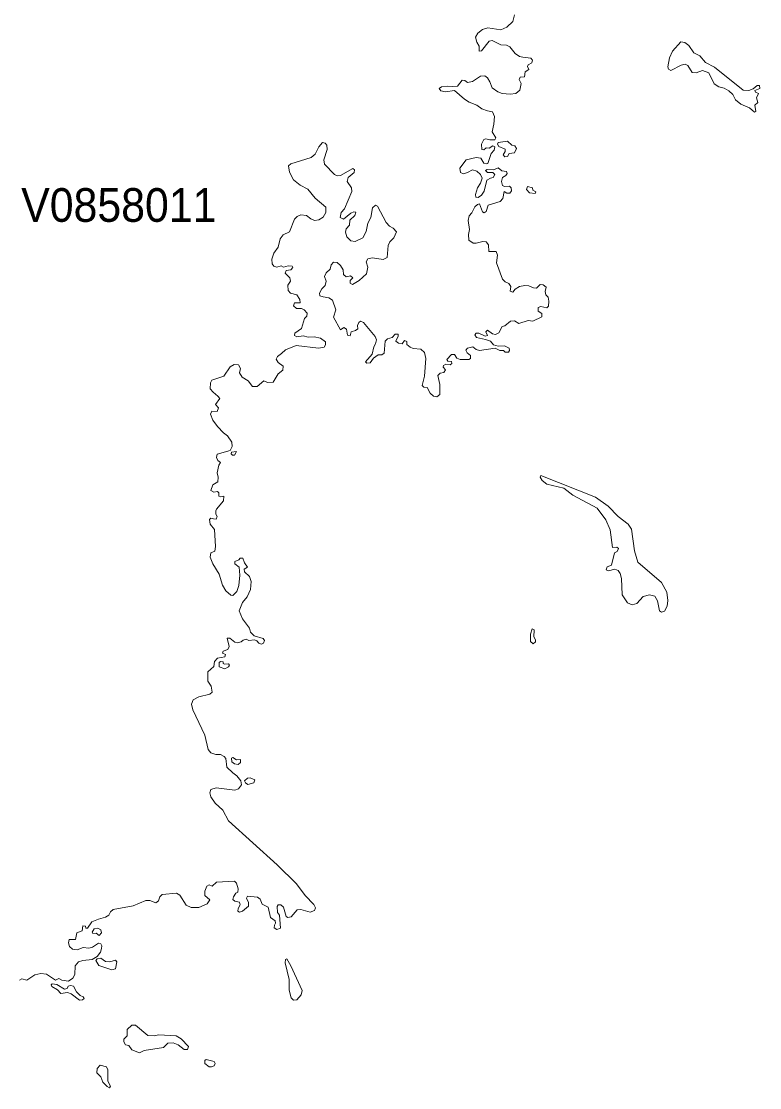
# Model space of a CAD drawing. Extents: x 369010 to 735936, y 6377141 to 6616555.
# Drawn here: x 436226 to 438417, y 6462420 to 6465583 of the extents above; entities that cross this region are included whole.
import ezdxf
from ezdxf.enums import TextEntityAlignment as Align

# ---------------------------------------------------------------- set-up
doc = ezdxf.new("R2010")
doc.units = 0
doc.header["$LTSCALE"] = 40
doc.layers.add('3', color=7, linetype='Continuous', lineweight=13)
doc.layers.add('4', color=7, linetype='Continuous')

msp = doc.modelspace()

# ---------------------------------------------------------------- linework, layer by layer
at = {"layer": '3'}
for points in [[(437718.53, 6465419), (437721.01, 6465433.56), (437731.6, 6465440.52), (437727.63, 6465448.96), (437729.78, 6465454.75), (437741.04, 6465459.88), (437742.86, 6465468.15), (437737.73, 6465473.95), (437713.73, 6465476.93), (437703.96, 6465479.41), (437691.22, 6465487.52), (437675.66, 6465507.54), (437665.73, 6465512.18), (437648.36, 6465514), (437623.2, 6465526.74), (437613.76, 6465524.59), (437591.59, 6465495.79), (437584.64, 6465494.8), (437584.64, 6465509.7), (437577.02, 6465521.61), (437573.38, 6465536.18), (437580.66, 6465547.93), (437594.07, 6465559.18), (437610.45, 6465563.82), (437649.02, 6465558.35), (437666.56, 6465566.46), (437683.94, 6465582.35), (437689.07, 6465602.87)], [(437594.57, 6465018.15), (437599.7, 6465015.67), (437605.49, 6465018.81), (437610.62, 6465038.17), (437647.03, 6465049.1), (437654.64, 6465057.87), (437658.95, 6465078.89), (437666.73, 6465073.76), (437675.33, 6465073.76), (437680.79, 6465080.05), (437679.8, 6465089.48), (437674.01, 6465094.12), (437659.44, 6465093.12), (437653.15, 6465096.43), (437650.67, 6465108.02), (437653.65, 6465120.43), (437663.75, 6465125.89), (437667.72, 6465132.02), (437665.24, 6465137.81), (437651.33, 6465139.63), (437640.91, 6465148.73), (437627.34, 6465142.61), (437608.47, 6465144.1), (437603.34, 6465140.46), (437609.13, 6465134.5), (437625.18, 6465135.33), (437630.65, 6465128.71), (437625.52, 6465120.1), (437618.23, 6465118.28), (437606.65, 6465111.99), (437599.7, 6465079.72), (437591.75, 6465067.97), (437581.49, 6465061.01), (437574.21, 6465061.84), (437573.22, 6465069.46), (437579.34, 6465089.81), (437587.95, 6465103.71), (437593.08, 6465118.28), (437588.28, 6465128.71), (437577.02, 6465138.64), (437564.28, 6465142.61), (437550.05, 6465134.99), (437538.13, 6465130.53), (437528.7, 6465134.99), (437526.88, 6465147.74), (437545.74, 6465172.73), (437575.53, 6465179.35), (437589.77, 6465177.53), (437598.54, 6465162.63), (437604.66, 6465160.48), (437610.12, 6465161.48), (437619.89, 6465191.27), (437629.32, 6465201.53), (437630.48, 6465210.96), (437624.69, 6465213.94), (437614.43, 6465206.99), (437605.32, 6465208.48), (437598.04, 6465201.86), (437591.92, 6465203.35), (437591.59, 6465219.4), (437598.04, 6465232.48), (437604.33, 6465234.3), (437616.25, 6465231.32), (437631.14, 6465231.65), (437633.46, 6465237.94), (437622.87, 6465255.32), (437628.33, 6465277.99), (437629.82, 6465301.16), (437624.36, 6465315.06), (437608.97, 6465317.55), (437591.92, 6465323.83), (437577.02, 6465335.09), (437555.18, 6465343.36), (437540.94, 6465352.14), (437510.82, 6465377.95), (437484.67, 6465373.98), (437470.77, 6465377.29), (437465.64, 6465384.08), (437472.26, 6465389.21), (437491.46, 6465391.03), (437506.02, 6465389.54), (437519.92, 6465391.03), (437534.16, 6465408.57), (437541.44, 6465407.75), (437549.71, 6465402.28), (437564.61, 6465404.6), (437588.61, 6465420.82), (437601.02, 6465421.98), (437608.63, 6465416.19), (437616.25, 6465403.77), (437623.2, 6465385.9), (437640.25, 6465373.98), (437652.99, 6465369.68), (437676.66, 6465367.03), (437692.71, 6465369.68), (437705.12, 6465379.44), (437709.1, 6465399.14), (437703.3, 6465410.72), (437706.45, 6465417.68), (437718.53, 6465419)], [(436982.37, 6464581.22), (436985.68, 6464589.49), (436998.09, 6464597.93), (437009.34, 6464609.19), (437041.78, 6464621.27), (437107.16, 6464613.49), (437124.7, 6464617.13), (437128.34, 6464624.08), (437128.67, 6464632.86), (437113.78, 6464643.45), (437095.24, 6464647.75), (437077.37, 6464646.76), (437062.47, 6464650.73), (437043.11, 6464647.42), (437036.32, 6464651.39), (437037.31, 6464658.34), (437056.68, 6464672.58), (437066.44, 6464701.54), (437073.39, 6464708.82), (437074.39, 6464717.26), (437064.95, 6464727.86), (437057.18, 6464731.17), (437042.11, 6464731), (437033.51, 6464739.77), (437036.82, 6464748.21), (437052.87, 6464747.88), (437052.04, 6464757.98), (437043.44, 6464772.21), (437024.74, 6464777.34), (437017.45, 6464784.62), (437016.79, 6464800.51), (437024.41, 6464812.26), (437022.92, 6464822.36), (437009.18, 6464835.93), (437011.99, 6464844.2), (437025.89, 6464846.36), (437031.03, 6464852.98), (437029.2, 6464856.95), (437017.45, 6464858.11), (437003.72, 6464853.64), (436997.1, 6464858.44), (436984.02, 6464853.64), (436974.59, 6464856.95), (436970.29, 6464864.23), (436969.46, 6464878.13), (436974.92, 6464895.51), (436987.66, 6464913.05), (436994.28, 6464937.71), (437002.56, 6464950.13), (437021.1, 6464959.23), (437036.49, 6464995.97), (437044.1, 6465004.25), (437055.35, 6465009.71), (437071.74, 6465006.89), (437084.48, 6464996.96), (437095.74, 6464992.99), (437108.15, 6464994.48), (437121.56, 6465002.1), (437129.17, 6465016.66), (437129.5, 6465031.89), (437097.39, 6465059.19), (437075.55, 6465085.51), (437053.37, 6465097.09), (437033.01, 6465112.82), (437021.43, 6465135.66), (437018.78, 6465154.19), (437025.07, 6465160.81), (437086.14, 6465179.02), (437097.72, 6465189.45), (437108.32, 6465210.96), (437119.57, 6465224.37), (437127.51, 6465222.22), (437132.64, 6465216.42), (437133.8, 6465203.35), (437123.87, 6465172.73), (437125.69, 6465159.99), (437155.15, 6465128.71), (437163.26, 6465125.06), (437173.03, 6465125.56), (437209.44, 6465147.24), (437214.9, 6465143.27), (437213.08, 6465134.5), (437196.03, 6465120.43), (437193.05, 6465108.68), (437205.47, 6465089.48), (437206.13, 6465078.56), (437184.28, 6465027.25), (437174.52, 6465016.33), (437172.37, 6465001.43), (437182.13, 6464995.97), (437203.98, 6465013.85), (437212.25, 6465018.48), (437218.54, 6465017.49), (437215.56, 6465007.56), (437201, 6464993.49), (437200, 6464978.43), (437189.41, 6464968), (437187.59, 6464957.41), (437191.56, 6464944.33), (437203.98, 6464931.92)], [(437462.16, 6464532.89), (437468.78, 6464539.68), (437479.54, 6464541.99), (437484.84, 6464549.28), (437477.56, 6464557.22), (437478.71, 6464562.68), (437485.66, 6464566.65), (437498.08, 6464564.17), (437503.04, 6464567.81), (437502.05, 6464573.94), (437491.13, 6464575.43), (437488.15, 6464580.06), (437502.38, 6464595.45), (437511.48, 6464594.62), (437518.1, 6464584.53), (437527.54, 6464580.06), (437553.69, 6464579.73), (437558.82, 6464582.71), (437559.15, 6464592.47), (437548.56, 6464599.75), (437544.92, 6464607.7), (437549.71, 6464613.99), (437565.77, 6464617.96), (437575.2, 6464609.52), (437584.97, 6464606.71), (437632.3, 6464613.99), (437645.38, 6464606.71), (437656.96, 6464606.71), (437661.76, 6464602.24), (437671.19, 6464601.91), (437674.5, 6464606.71), (437673.02, 6464613.66), (437659.61, 6464620.44), (437640.58, 6464620.11), (437627.17, 6464624.08), (437617.74, 6464634.35), (437603.5, 6464639.48), (437576.69, 6464645.6), (437571.56, 6464652.88), (437575.86, 6464658.34), (437583.81, 6464658.01), (437602.51, 6464649.24), (437608.97, 6464651.06), (437604.33, 6464662.65), (437608.63, 6464666.78), (437623.86, 6464655.86), (437633.29, 6464654.04), (437643.22, 6464659.5), (437652.33, 6464677.71), (437660.6, 6464680.19), (437677.81, 6464693.6), (437689.07, 6464694.75), (437702.14, 6464687.14), (437730.11, 6464696.24), (437743.19, 6464693.6), (437770.83, 6464706.34), (437770.83, 6464716.27), (437759.9, 6464723.88), (437759.9, 6464734.31), (437767.19, 6464736.96), (437785.39, 6464732.99), (437790.52, 6464738.45), (437790.85, 6464753.34), (437788.7, 6464764.93), (437781.75, 6464771.55), (437780.26, 6464781.64), (437783.57, 6464794.72), (437773.81, 6464802), (437765.7, 6464802.5), (437754.94, 6464792.24), (437745.34, 6464792.9), (437732.1, 6464799.19), (437719.69, 6464799.85), (437703.8, 6464797.04), (437690.72, 6464789.26), (437684.77, 6464780.15), (437676.49, 6464782.47), (437678.31, 6464796.54), (437672.85, 6464805.31), (437661.6, 6464810.11), (437653.49, 6464818.05), (437635.45, 6464867.21), (437638.59, 6464889.72), (437634.62, 6464900.31), (437612.77, 6464900.97), (437612.44, 6464920.34), (437605.49, 6464929.11), (437595.39, 6464929.77), (437575.37, 6464924.97), (437566.27, 6464924.97), (437554.18, 6464934.4), (437553.19, 6464950.79), (437556, 6464965.35), (437552.03, 6464992.33), (437554.68, 6465006.07), (437562.79, 6465015.17), (437571.73, 6465032.71), (437579.01, 6465040.33), (437585.46, 6465041.82), (437594.57, 6465018.15)], [(437203.98, 6464931.92), (437216.72, 6464929.77), (437238.9, 6464941.02), (437248.99, 6464959.56), (437253.79, 6464984.39), (437262.9, 6465001.43), (437268.03, 6465030.23), (437276.63, 6465037.51), (437282.59, 6465035.2), (437308.74, 6464986.54), (437317.84, 6464975.95), (437329.43, 6464969.33), (437339.36, 6464958.57), (437331.25, 6464940.69), (437319.5, 6464928.94), (437314.04, 6464918.18), (437311.39, 6464883.1), (437299.47, 6464876.97), (437267.37, 6464881.77), (437253.96, 6464878.46), (437248.83, 6464870.02), (437253.96, 6464854.47), (437249.99, 6464834.44), (437228.47, 6464814.41), (437208.45, 6464802.83), (437201.66, 6464806.8), (437201.99, 6464814.74), (437209.27, 6464822.85), (437202.98, 6464828.65), (437189.91, 6464825.67), (437181.63, 6464832.29), (437180.48, 6464845.69), (437173.19, 6464859.1), (437163.1, 6464868.2), (437152.51, 6464868.7), (437145.55, 6464860.59), (437142.24, 6464848.34), (437130, 6464837.42), (437125.86, 6464826.83), (437130, 6464812.26), (437127.68, 6464799.85), (437117.91, 6464790.08), (437110.63, 6464777.01), (437111.79, 6464768.9), (437121.23, 6464765.59), (437138.27, 6464763.11), (437148.86, 6464755.83), (437158.63, 6464727.52), (437152.51, 6464705.35), (437172.53, 6464667.78), (437182.96, 6464675.39), (437190.41, 6464670.43), (437193.72, 6464652.55), (437201.33, 6464649.9), (437204.97, 6464661.98), (437217.38, 6464665.96), (437224.33, 6464671.42), (437223.18, 6464680.85), (437227.15, 6464690.29), (437232.28, 6464693.6), (437241.05, 6464689.95), (437275.97, 6464648.58), (437279.28, 6464638.32), (437276.63, 6464626.73), (437271.5, 6464617.63), (437266.87, 6464596.44), (437247.17, 6464573.61), (437251.15, 6464568.81), (437261.08, 6464570.63), (437271.17, 6464584.53), (437284.25, 6464594.29), (437296, 6464593.63), (437302.78, 6464598.76), (437305.76, 6464634.35), (437312.38, 6464641.96), (437326.45, 6464644.94), (437335.55, 6464655.36), (437343.99, 6464655.03), (437343.99, 6464648.91), (437337.37, 6464634.68), (437344.66, 6464628.88), (437355.91, 6464626.4), (437362.53, 6464636.17), (437369.48, 6464634.01), (437369.81, 6464624.58), (437379.25, 6464616.8), (437388.35, 6464612.5), (437411.35, 6464610.68), (437422.61, 6464600.58), (437426.25, 6464583.37), (437422.61, 6464530.57), (437415.33, 6464502.6), (437419.96, 6464498.3), (437430.22, 6464496.81), (437439.32, 6464480.76), (437448.76, 6464471.65), (437458.85, 6464469.83), (437467.62, 6464476.45), (437467.96, 6464505.91), (437462.16, 6464532.89)], [(436938.51, 6463735.66), (436944.8, 6463738.97), (436946.95, 6463746.58), (436943.64, 6463752.37), (436917.16, 6463760.32), (436905.9, 6463770.91), (436903.26, 6463783.65), (436881.91, 6463811.29), (436872.31, 6463834.3), (436882.57, 6463858.96), (436895.97, 6463876.5), (436905.41, 6463897.85), (436907.72, 6463922.02), (436902.59, 6463936.91), (436888.03, 6463950.32), (436887.37, 6463957.93), (436896.47, 6463964.55), (436887.7, 6463977.29), (436882.9, 6463990.7), (436875.62, 6463991.03), (436871.65, 6463985.57), (436859.23, 6463980.94), (436859.23, 6463974.32), (436871.98, 6463963.72), (436874.62, 6463940.88), (436871.65, 6463909.6), (436865.19, 6463892.39), (436853.77, 6463880.47), (436847.32, 6463880.81), (436832.42, 6463893.88), (436822.99, 6463910.27), (436812.89, 6463943.04), (436793.69, 6463973.65), (436786.41, 6463994.01), (436788.56, 6464006.42), (436799.82, 6464011.88), (436802.3, 6464025.62), (436798.66, 6464075.44), (436785.91, 6464091.82), (436784.09, 6464105.73), (436788.56, 6464109.37), (436795.84, 6464107.05), (436803.46, 6464106.06), (436806.77, 6464114.83), (436802.8, 6464120.95), (436802.8, 6464131.21), (436804.45, 6464136.67), (436825.97, 6464161), (436826.3, 6464174.41), (436816.53, 6464172.92), (436812.23, 6464175.24), (436812.23, 6464184.67), (436808.09, 6464188.31), (436797.33, 6464186.49), (436787.73, 6464191.62), (436793.69, 6464208.34), (436808.92, 6464216.94), (436809.91, 6464231.51), (436807.1, 6464244.25), (436812.23, 6464266.93), (436816.53, 6464274.54), (436809.25, 6464280.33), (436804.95, 6464289.43), (436806.77, 6464299.2), (436845.33, 6464309.79), (436851.12, 6464321.71), (436850.79, 6464334.95), (436838.05, 6464353.82), (436825.97, 6464362.92), (436807.43, 6464381.46), (436794.02, 6464400.32), (436787.07, 6464417.87), (436790.71, 6464426.64), (436807.1, 6464426.14), (436811.07, 6464436.4), (436802.3, 6464446.99), (436814.38, 6464464.04), (436808.92, 6464471.65), (436795.02, 6464482.91), (436786.41, 6464492.84), (436786.74, 6464510.55), (436791.04, 6464519.32), (436826.3, 6464530.24), (436845.33, 6464558.21), (436857.25, 6464565.16), (436870.32, 6464564.17), (436876.28, 6464553.91), (436873.63, 6464540.84), (436881.24, 6464528.09), (436899.12, 6464517.17), (436912.19, 6464500.45), (436925.27, 6464499.62), (436944.96, 6464516.84), (436956.55, 6464512.37), (436972.6, 6464513.2), (436987.5, 6464537.53), (437001.73, 6464548.45), (437003.22, 6464560.86), (436988.16, 6464570.96), (436982.37, 6464581.22)], [(436792.04, 6463017.87), (436804.45, 6463029.78), (436857.91, 6463032.76), (436864.69, 6463026.64), (436869.49, 6463009.76), (436868, 6462999.66), (436861.88, 6462996.68), (436854.93, 6462985.76), (436853.77, 6462978.15), (436858.9, 6462973.18), (436872.8, 6462970.53), (436875.62, 6462962.59), (436868.83, 6462952), (436868, 6462943.56), (436873.47, 6462940.74), (436882.57, 6462944.05), (436899.62, 6462958.95), (436900.11, 6462969.54), (436894.15, 6462982.12), (436897.13, 6462988.08), (436926.26, 6462985.43), (436934.21, 6462979.31), (436940, 6462964.41), (436958.53, 6462955.64), (436965.15, 6462924.69), (436979.06, 6462915.26), (436980.38, 6462908.3), (436976.74, 6462902.18), (436975.75, 6462894.07), (436983.69, 6462889.44), (436994.95, 6462893.41), (436991.64, 6462931.64), (436985.51, 6462939.25), (436984.85, 6462957.13), (436988.16, 6462962.59), (436995.77, 6462962.59), (437004.05, 6462955.31), (437011.33, 6462928), (437016.79, 6462924.69), (437026.72, 6462927.34), (437044.76, 6462948.03), (437054.69, 6462948.69), (437082.66, 6462941.07), (437095.41, 6462945.87), (437098.72, 6462953.82), (437094.25, 6462963.58), (437068.43, 6462990.23), (437041.95, 6463024.82), (436984.85, 6463081.59), (436840.2, 6463211.34), (436823.81, 6463243.45), (436801.31, 6463264.14), (436787.73, 6463283.01), (436784.92, 6463294.42), (436788.56, 6463304.19), (436803.79, 6463309.98), (436859.07, 6463302.37), (436869.99, 6463306.34), (436879.09, 6463318.42), (436877.6, 6463330.67), (436865.36, 6463344.9), (436853.27, 6463353.68), (436835.23, 6463370.72), (436832.75, 6463396.21), (436827.62, 6463402.33), (436816.7, 6463408.29), (436802.96, 6463408.29), (436788.4, 6463413.75), (436779.96, 6463423.19), (436770.52, 6463465.72), (436734.94, 6463541.03), (436730.8, 6463558.07), (436735.6, 6463570.49), (436752.98, 6463579.26), (436785.09, 6463587.2), (436792.04, 6463593.49), (436789.39, 6463611.53), (436778.96, 6463626.09), (436779.62, 6463653.4), (436796.67, 6463669.79), (436799.32, 6463684.35), (436807.59, 6463694.12), (436829.44, 6463697.76), (436831.59, 6463704.71), (436822.49, 6463708.68), (436824.64, 6463715.3), (436838.88, 6463719.6), (436842.85, 6463728.38), (436836.72, 6463753.2), (436844.67, 6463753.86), (436859.73, 6463741.78), (436866.51, 6463739.96), (436878.27, 6463742.61), (436884.06, 6463747.74), (436893.16, 6463750.22), (436900.77, 6463746.58), (436917.49, 6463748.73), (436925.1, 6463745.92), (436930.9, 6463738.64), (436938.51, 6463735.66)], [(436220.55, 6462739.16), (436227.34, 6462743.13), (436241.9, 6462738.5), (436265.9, 6462754.88), (436283.77, 6462758.85), (436300.82, 6462756.7), (436327.14, 6462739.16), (436336.9, 6462743.46), (436346, 6462739.16), (436366.03, 6462735.85), (436378.44, 6462744.62), (436384.9, 6462755.54), (436385.73, 6462781.36), (436395.49, 6462793.28), (436407.9, 6462797.75), (436435.87, 6462799.9), (436451.1, 6462809.66), (436460.53, 6462822.08), (436463.84, 6462833.33), (436465, 6462840.61), (436462.02, 6462846.9), (436454.41, 6462849.05), (436437.36, 6462836.97), (436426.44, 6462833.83), (436408.9, 6462835.65), (436391.19, 6462829.36), (436377.62, 6462830.52), (436368.51, 6462838.46), (436365.37, 6462849.72), (436368.18, 6462859.65), (436386.06, 6462859.15), (436390.36, 6462879.18), (436406.41, 6462885.8), (436407.9, 6462900.36), (436416.18, 6462899.53), (436417.34, 6462893.08), (436422.47, 6462893.41), (436434.71, 6462911.61), (436455.07, 6462920.05), (436475.1, 6462925.85), (436485.03, 6462931.97), (436490.49, 6462941.4), (436498.1, 6462948.36), (436558.01, 6462959.61), (436595.25, 6462975.33), (436607.17, 6462975.66), (436624.71, 6462968.71), (436632.99, 6462974.17), (436636.63, 6462986.26), (436643.58, 6462993.54), (436686.45, 6462997.51), (436695.88, 6462990.89), (436714.58, 6462961.43), (436729.48, 6462954.15), (436752.65, 6462954.98), (436777.14, 6462965.07), (436784.76, 6462977.15), (436770.52, 6462990.56), (436770.19, 6463003.3), (436775.98, 6463018.2), (436782.93, 6463022.17), (436792.04, 6463017.87)]]:
    msp.add_lwpolyline(points, dxfattribs=at)
for points in [[(438401.56, 6465314.07), (438405.54, 6465315.89), (438402.72, 6465334.43), (438411.33, 6465342.7), (438407.36, 6465356.27), (438413.65, 6465369.68), (438404.21, 6465372.99), (438402.72, 6465377.95), (438416.79, 6465384.24), (438415.8, 6465393.02), (438408.85, 6465393.02), (438397.26, 6465383.09), (438384.19, 6465378.45), (438367.47, 6465379.44), (438282.9, 6465447.14), (438256.25, 6465461.04), (438239.2, 6465480.9), (438221, 6465489.67), (438206.43, 6465511.85), (438194.52, 6465520.95), (438182.44, 6465522.77), (438157.78, 6465494.47), (438149.67, 6465475.11), (438144.54, 6465448.29), (438146.03, 6465441.01), (438153.31, 6465437.7), (438183.93, 6465453.76), (438195.51, 6465455.91), (438203.12, 6465452.27), (438216.2, 6465431.91), (438227.95, 6465430.09), (438247.31, 6465437.04), (438266.35, 6465430.75), (438281.9, 6465397.98), (438295.81, 6465388.55), (438311.36, 6465385.24), (438325.6, 6465377.29), (438336.85, 6465366.04), (438345.29, 6465350.81), (438360.85, 6465338.07), (438386.67, 6465326.65)], [(437668.38, 6465227.68), (437641.07, 6465224.04), (437638.92, 6465218.91), (437643.22, 6465212.45), (437661.76, 6465204.01), (437661.76, 6465197.56), (437655.97, 6465187.63), (437660.6, 6465181.17), (437668.38, 6465182.66), (437673.68, 6465190.94), (437689.07, 6465193.58), (437694.86, 6465205.83), (437690.06, 6465213.94), (437680.96, 6465216.09)], [(437750.64, 6465072.43), (437752.46, 6465077.23), (437744.02, 6465082.36), (437742.53, 6465089.65), (437728.29, 6465093.62), (437724.65, 6465084.85), (437733.42, 6465074.59)], [(436864.2, 6464307.64), (436848.97, 6464305.49), (436848.14, 6464300.03), (436852.61, 6464296.39), (436858.74, 6464296.72)], [(438125.34, 6463830.33), (438133.94, 6463833.64), (438142.38, 6463848.2), (438144.21, 6463865.58), (438140.9, 6463889.58), (438125.34, 6463919.04), (438055.16, 6463979.45), (438045.73, 6464012.55), (438036.79, 6464076.93), (438026.37, 6464091.99), (437997.24, 6464114.83), (437966.95, 6464145.45), (437929.38, 6464171.93), (437767.85, 6464235.98), (437765.53, 6464230.85), (437771.66, 6464221.08), (437785.39, 6464210.82), (437835.71, 6464198.08), (437862.19, 6464177.39), (437934.84, 6464139.16), (437959.83, 6464104.24), (437973.24, 6464074.78), (437980.52, 6464022.81), (437992.77, 6464023.8), (437997.57, 6464019.17), (437994.26, 6464010.73), (437986.31, 6464006.75), (437976.72, 6463970.01), (437964.3, 6463965.21), (437961.32, 6463956.11), (437968.61, 6463953.3), (437987.14, 6463958.43), (437997.07, 6463954.45), (438002.86, 6463945.68), (438006.51, 6463930.29), (438008.99, 6463881.63), (438025.04, 6463858.3), (438037.95, 6463852.5), (438052.19, 6463856.81), (438070.72, 6463876.83), (438089.59, 6463882.3), (438105.97, 6463877.99), (438113.92, 6463864.42), (438119.88, 6463834.3)], [(437744.84, 6463736.82), (437751.46, 6463742.28), (437751.8, 6463748.4), (437746.66, 6463757.51), (437747.49, 6463778.19), (437742.03, 6463780.84), (437736.57, 6463765.12), (437736.24, 6463743.27)], [(436829.44, 6463662.17), (436840.7, 6463668.3), (436843.67, 6463673.43), (436840.7, 6463677.4), (436829.11, 6463676.74), (436825.14, 6463678.56), (436824.31, 6463683.69), (436816.7, 6463684.02), (436812.73, 6463681.04), (436812.73, 6463668.79)], [(436869.33, 6463379.16), (436875.78, 6463384.96), (436875.78, 6463394.06), (436864.2, 6463392.9), (436852.94, 6463399.52), (436849.3, 6463398.03), (436850.46, 6463386.45), (436858.4, 6463380.65)], [(436904.91, 6463338.78), (436897.3, 6463337.95), (436888.2, 6463330.01), (436890.68, 6463324.22), (436897.63, 6463319.75), (436915.83, 6463323.88), (436918.81, 6463333.32)], [(436456.89, 6462871.23), (436463.51, 6462879.18), (436461.36, 6462888.28), (436453.25, 6462892.75), (436442, 6462891.26), (436436.2, 6462881.82), (436437.69, 6462877.35), (436447.46, 6462878.84)], [(436494.3, 6462769.78), (436505.22, 6462772.26), (436509.19, 6462793.44), (436505.55, 6462798.41), (436488.34, 6462792.95), (436475.26, 6462794.77), (436461.53, 6462804.7), (436450.93, 6462802.55), (436446.96, 6462797.42), (436455.73, 6462782.02)], [(437033.18, 6462679.91), (437043.44, 6462680.9), (437056.18, 6462695.8), (437059, 6462708.54), (437025.89, 6462781.69), (437013.48, 6462802.05), (437009.51, 6462799.9), (437009.18, 6462790.8), (437020.43, 6462741.31), (437020.1, 6462709.04), (437026.23, 6462686.69)], [(436407.74, 6462680.9), (436412.04, 6462684.87), (436409.56, 6462689.67), (436400.46, 6462693.31), (436389.86, 6462703.91), (436380.43, 6462721.28), (436371.66, 6462723.44), (436365.04, 6462720.95), (436361.4, 6462714), (436353.45, 6462712.18), (436330.94, 6462726.08), (436317.37, 6462728.24), (436314.23, 6462725.26), (436316.05, 6462719.8), (436333.43, 6462710.36), (436342.86, 6462699.11), (436362.55, 6462702.42), (436373.81, 6462698.11), (436398.14, 6462679.91)], [(436576.05, 6462523.01), (436589.96, 6462530.62), (436647.55, 6462539.06), (436660.96, 6462552.14), (436676.68, 6462553.3), (436690.91, 6462547.34), (436709.45, 6462532.94), (436719.22, 6462533.27), (436721.37, 6462542.37), (436699.69, 6462564.88), (436685.45, 6462573.65), (436632.49, 6462576.8), (436621.24, 6462573.99), (436600.88, 6462574.98), (436564.47, 6462605.27), (436553.55, 6462605.6), (436540.14, 6462592.85), (436539.64, 6462573.65), (436530.21, 6462563.72), (436530.21, 6462555.78), (436535.01, 6462547.34), (436544.44, 6462544.86), (436553.55, 6462532.11)], [(436487.84, 6462420.07), (436490.49, 6462424.37), (436482.38, 6462439.43), (436482.05, 6462473.19), (436478.74, 6462481.97), (436460.2, 6462486.93), (436450.44, 6462476.5), (436450.11, 6462464.42), (436462.02, 6462452.01), (436467.48, 6462436.45), (436480.56, 6462423.38)], [(436790.05, 6462481.63), (436798.33, 6462484.78), (436801.31, 6462491.4), (436798, 6462497.52), (436774.66, 6462503.32), (436770.69, 6462500.5), (436770.69, 6462491.4), (436782.77, 6462482.3)]]:
    msp.add_lwpolyline(points, close=True, dxfattribs=at)

# ---------------------------------------------------------------- texts
at = {"layer": '4', "width": 0.95}
msp.add_text('V0858011', height=100, dxfattribs=at).set_placement((436515.04, 6464988.52), align=Align.CENTER)

doc.saveas('drawing.dxf')
